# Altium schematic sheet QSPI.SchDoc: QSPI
size A4; DocumentNumber: MB1144; Revision: C-02; SheetNumber: 13; SheetTotal: 25; Project: STM32L476G-EVAL
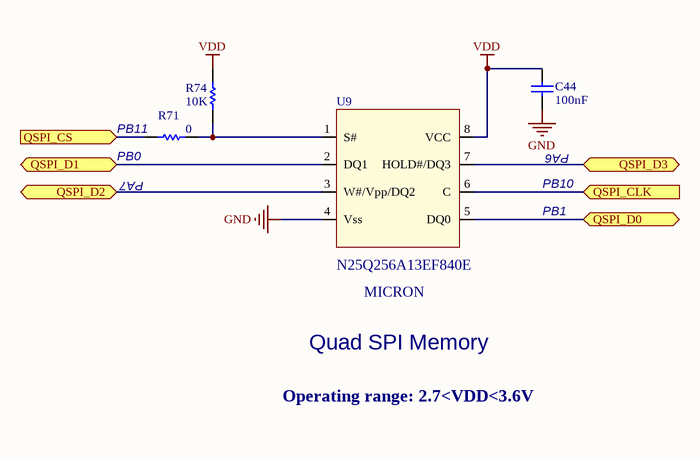
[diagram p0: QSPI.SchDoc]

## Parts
C44  100nF  [0402C]
R71  0  [0603R]
R74  10K  [0402R]
U9  N25Q256A13EF840E  [DFN8_1R27_6X8_TP4R8X5R8]

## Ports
QSPI_CLK (in), QSPI_CS (in), QSPI_D0 (bidir), QSPI_D1 (bidir), QSPI_D2 (bidir), QSPI_D3 (bidir)

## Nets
GND: C44.2 U9.4(Vss)
VDD: C44.1 R74.1 U9.8(VCC)
QSPI_CLK: U9.6(C) ; port QSPI_CLK
QSPI_CS: R71.2 ; port QSPI_CS
QSPI_D0: U9.5(DQ0) ; port QSPI_D0
QSPI_D1: U9.2(DQ1) ; port QSPI_D1
QSPI_D2: U9.3(W#/Vpp/DQ2) ; port QSPI_D2
QSPI_D3: U9.7(HOLD#/DQ3) ; port QSPI_D3
NetR71_1: R71.1 R74.2 U9.1(S#)

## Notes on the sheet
- (near R71) PB0
- (near R71) PB11
- PA6
- (near R71) PA7
- PB1
- PB10
- MICRON
- Quad SPI Memory
- Operating range: 2.7<VDD<3.6V

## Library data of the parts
C44 = Cap: Capacitor; Value: 10nF; Ordered by: Subcon; ECCN_US/EU: NA
R71 = Res1: Resistor; Value: 1K; Ordered by: Subcon; ECCN_US/EU: NA
R74 = res1: Resistor; Value: 1K; Ordered by: Subcon; ECCN_US/EU: NA
U9 = QSPI_8pins: Manuf_1: Micron; ECCN_US/EU: 3A991; Ordered by: Subcon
